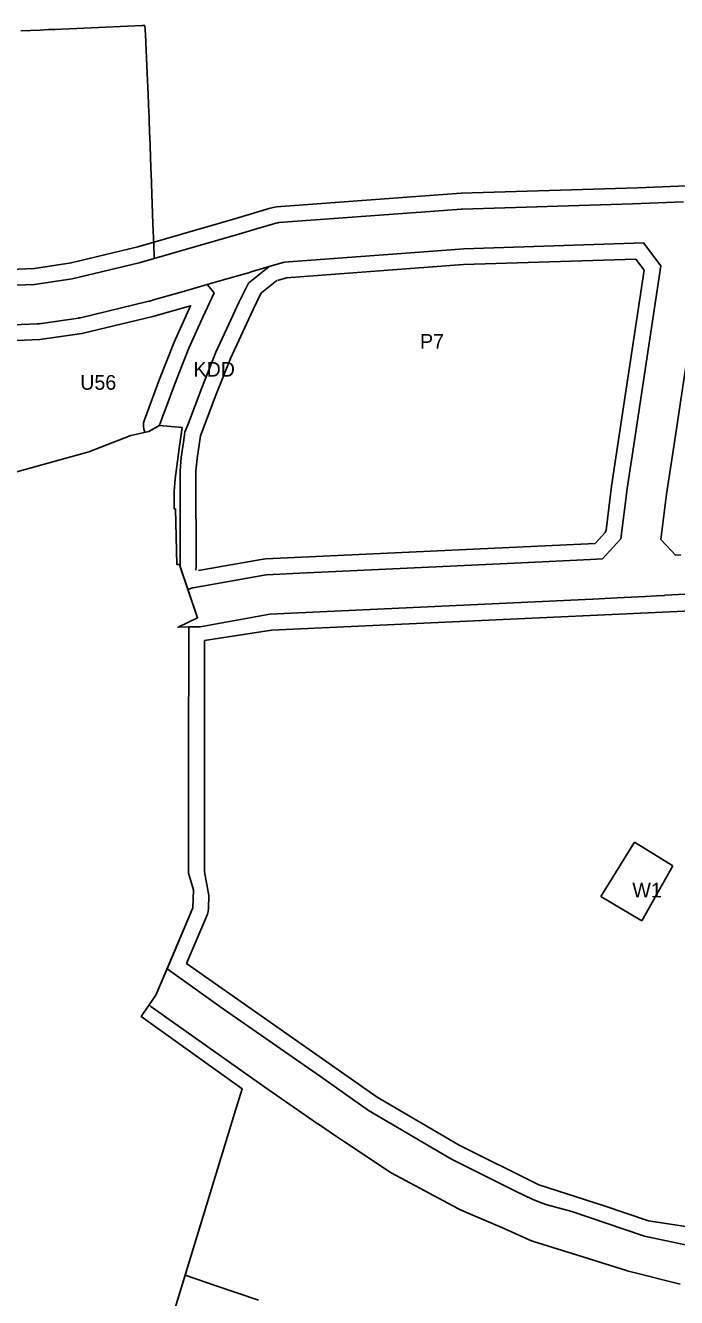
# Model space of a CAD drawing. Extents: x 7428103 to 7431580, y 5545880 to 5549002.
# Drawn here: x 7428892.8 to 7429139.1, y 5546219.5 to 5546701.1 of the extents above; entities that cross this region are included whole.
import ezdxf

# ---------------------------------------------------------------- set-up
doc = ezdxf.new("R2010")
doc.units = 0
for name, color, linetype in [('CZ_L_granica obszaru objętego planem', 7, 'Continuous'), ('CZ_L_linie rozgraniczające tereny o różnym przeznaczeniu oraz różnych warunkach ich zabudowy i zagospodarowania', 7, 'Continuous'), ('CZ_L_maksymalne nieprzekraczalne linie zabudowy', 7, 'Continuous'), ('CZ_L_opisy_linie rozgraniczające tereny o różnym przeznaczeniu oraz różnych warunkach ich zabudowy i zagospodarowania', 7, 'Continuous')]:
    doc.layers.add(name, color=color, linetype=linetype)

msp = doc.modelspace()

# ---------------------------------------------------------------- linework, layer by layer
at = {"layer": 'CZ_L_granica obszaru objętego planem'}
for p, q in [((7428943.45, 5546549.68), (7428939.45, 5546547.36)), ((7428952.02, 5546548.83), (7428943.45, 5546549.68)), ((7428932.66, 5546545.89), (7428916.75, 5546539.71)), ((7428939.45, 5546547.36), (7428932.66, 5546545.89)), ((7428950.98, 5546540.88), (7428952.02, 5546548.83)), ((7428949.49, 5546529.49), (7428950.98, 5546540.88)), ((7428916.75, 5546539.71), (7428884.44, 5546530.73)), ((7428949.1, 5546524.59), (7428949.49, 5546529.49)), ((7428949.01, 5546518.1), (7428949.1, 5546524.59)), ((7428949.54, 5546518.02), (7428949.01, 5546518.1)), ((7428950.1, 5546497), (7428949.54, 5546518.02)), ((7428951.06, 5546497.01), (7428950.1, 5546497)), ((7428957.94, 5546476.87), (7428951.06, 5546497.01)), ((7428950.54, 5546473.28), (7428957.94, 5546476.87)), ((7428954.57, 5546473.36), (7428950.54, 5546473.28)), ((7428954.56, 5546462.58), (7428954.57, 5546473.36)), ((7428954.53, 5546431.49), (7428954.56, 5546462.58)), ((7428954.53, 5546422.43), (7428954.53, 5546431.49)), ((7428954.49, 5546380.11), (7428954.53, 5546422.43)), ((7428956.31, 5546373.9), (7428954.49, 5546380.11)), ((7428956.09, 5546367.01), (7428956.31, 5546373.9)), ((7428942.16, 5546333.95), (7428956.09, 5546367.01)), ((7428936.55, 5546325.96), (7428942.16, 5546333.95)), ((7428974.81, 5546298.48), (7428936.55, 5546325.96)), ((7428971.91, 5546289.21), (7428974.81, 5546298.48)), ((7428945.19, 5546201.63), (7428971.91, 5546289.21))]:
    msp.add_line(p, q, dxfattribs=at)
at = {"layer": 'CZ_L_linie rozgraniczające tereny o różnym przeznaczeniu oraz różnych warunkach ich zabudowy i zagospodarowania'}
for p, q in [((7428891.05, 5546699.01), (7428898.31, 5546699.33)), ((7428898.31, 5546699.33), (7428901.54, 5546699.47)), ((7428901.54, 5546699.47), (7428903.86, 5546699.57)), ((7428903.86, 5546699.57), (7428906.43, 5546699.68)), ((7428906.43, 5546699.68), (7428912.22, 5546699.93)), ((7428912.22, 5546699.93), (7428914.83, 5546700.04)), ((7428914.83, 5546700.04), (7428936.95, 5546701.01)), ((7428936.95, 5546701.01), (7428937.99, 5546701.06)), ((7428937.99, 5546701.06), (7428938.15, 5546697.68)), ((7428938.15, 5546697.68), (7428938.72, 5546685.73)), ((7428938.72, 5546685.73), (7428939.25, 5546674.93)), ((7428939.25, 5546674.93), (7428939.52, 5546667.84)), ((7428939.52, 5546667.84), (7428939.52, 5546667.82)), ((7428939.52, 5546667.82), (7428939.55, 5546666.83)), ((7428939.55, 5546666.83), (7428939.62, 5546665.02)), ((7428939.62, 5546665.02), (7428939.63, 5546664.67)), ((7428939.63, 5546664.67), (7428939.86, 5546658.05)), ((7428939.86, 5546658.05), (7428939.88, 5546657.66)), ((7428939.88, 5546657.66), (7428939.91, 5546656.76)), ((7428939.91, 5546656.76), (7428939.95, 5546655.47)), ((7428939.95, 5546655.47), (7428940.25, 5546647.15)), ((7428940.25, 5546647.15), (7428940.43, 5546641.82)), ((7428940.43, 5546641.82), (7428940.45, 5546641.26)), ((7428940.45, 5546641.26), (7428941.03, 5546626.01)), ((7429047.51, 5546630.72), (7429057.66, 5546631.51)), ((7429057.66, 5546631.51), (7429057.94, 5546631.53)), ((7429057.94, 5546631.53), (7429058.01, 5546631.53)), ((7429058.01, 5546631.53), (7429122.49, 5546633.57)), ((7429122.49, 5546633.57), (7429141.68, 5546634.33)), ((7428988.69, 5546626.41), (7429047.51, 5546630.72)), ((7428941.03, 5546626.01), (7428941.33, 5546618.11)), ((7428941.52, 5546612.85), (7428973.83, 5546622.12)), ((7428973.83, 5546622.12), (7428980.19, 5546624.04)), ((7428980.19, 5546624.04), (7428987.08, 5546626.11)), ((7428987.08, 5546626.11), (7428987.48, 5546626.22)), ((7428987.48, 5546626.22), (7428987.96, 5546626.32)), ((7428987.96, 5546626.32), (7428988.44, 5546626.39)), ((7428988.44, 5546626.39), (7428988.69, 5546626.41)), ((7428941.33, 5546618.11), (7428941.51, 5546613.1)), ((7429058.66, 5546616.55), (7429123, 5546618.58)), ((7429123, 5546618.58), (7429123.05, 5546618.58)), ((7429123.05, 5546618.58), (7429126.59, 5546618.72)), ((7429126.59, 5546618.72), (7429133.16, 5546610.02)), ((7428941.52, 5546612.85), (7428935.83, 5546611.21)), ((7428941.51, 5546613.1), (7428941.52, 5546612.85)), ((7428990.61, 5546611.51), (7429048.63, 5546615.76)), ((7429048.63, 5546615.76), (7429048.67, 5546615.76)), ((7429048.67, 5546615.76), (7429058.66, 5546616.55)), ((7428933.17, 5546610.57), (7428910.44, 5546605.09)), ((7428935.83, 5546611.21), (7428933.17, 5546610.57)), ((7428966.36, 5546604.37), (7428978.01, 5546607.72)), ((7428977.13, 5546603.54), (7428984.97, 5546609.81)), ((7428978.01, 5546607.72), (7428978.1, 5546607.75)), ((7428978.1, 5546607.75), (7428979.39, 5546608.14)), ((7428979.39, 5546608.14), (7428984.97, 5546609.81)), ((7428984.97, 5546609.81), (7428990.61, 5546611.51)), ((7429133.16, 5546610.02), (7429123.46, 5546545.53)), ((7429138.29, 5546543.29), (7429148.42, 5546610.65)), ((7428896.25, 5546603.05), (7428868.81, 5546601.94)), ((7428910.44, 5546605.09), (7428896.25, 5546603.05)), ((7428958.12, 5546602.01), (7428961.54, 5546602.99)), ((7428961.54, 5546602.99), (7428966.36, 5546604.37)), ((7428961.54, 5546602.99), (7428964.15, 5546599.8)), ((7428973.47, 5546596.13), (7428977.13, 5546603.54)), ((7428941.17, 5546597.14), (7428951.18, 5546600.01)), ((7428951.18, 5546600.01), (7428958.12, 5546602.01)), ((7428964.15, 5546599.8), (7428959.85, 5546590.57)), ((7428913.61, 5546590.43), (7428933.74, 5546595.28)), ((7428933.74, 5546595.28), (7428939.5, 5546596.67)), ((7428939.5, 5546596.67), (7428939.81, 5546596.75)), ((7428939.5, 5546596.67), (7428939.5, 5546596.67)), ((7428939.81, 5546596.75), (7428941.17, 5546597.14)), ((7428968.92, 5546586.35), (7428973.47, 5546596.13)), ((7428870.63, 5546587), (7428897.25, 5546588.08)), ((7428897.25, 5546588.08), (7428897.73, 5546588.12)), ((7428897.73, 5546588.12), (7428898.01, 5546588.15)), ((7428898.01, 5546588.15), (7428912.92, 5546590.29)), ((7428912.92, 5546590.29), (7428913.13, 5546590.33)), ((7428913.13, 5546590.33), (7428913.61, 5546590.43)), ((7428959.85, 5546590.57), (7428954.59, 5546578.93)), ((7428964.83, 5546577.37), (7428968.92, 5546586.35)), ((7428954.59, 5546578.93), (7428951.09, 5546569.95)), ((7428959.51, 5546563.93), (7428964.83, 5546577.37)), ((7428951.09, 5546569.95), (7428949.15, 5546565)), ((7428949.15, 5546565), (7428945.87, 5546556.18)), ((7428954.42, 5546550.54), (7428959.51, 5546563.93)), ((7428945.87, 5546556.18), (7428944.65, 5546552.89)), ((7428943.72, 5546550.39), (7428943.41, 5546549.66)), ((7428944.65, 5546552.89), (7428943.72, 5546550.39)), ((7428953.11, 5546547.07), (7428954.42, 5546550.54)), ((7428952.53, 5546543.28), (7428953.11, 5546547.07)), ((7429123.46, 5546545.53), (7429120.42, 5546525.82)), ((7428951.73, 5546537.49), (7428952.53, 5546543.28)), ((7429135.26, 5546523.65), (7429138.29, 5546543.27)), ((7429138.29, 5546543.27), (7429138.29, 5546543.29)), ((7428951.3, 5546532.51), (7428951.73, 5546537.49)), ((7428951.36, 5546528.96), (7428951.3, 5546532.51)), ((7428951.34, 5546519.82), (7428951.36, 5546528.96)), ((7429120.39, 5546525.59), (7429118.07, 5546506.75)), ((7429120.42, 5546525.82), (7429120.39, 5546525.59)), ((7429133.15, 5546506.5), (7429135.26, 5546523.65)), ((7428951.34, 5546510.5), (7428951.34, 5546519.82)), ((7428951.37, 5546498.1), (7428951.34, 5546510.5)), ((7429118.07, 5546506.75), (7429111.13, 5546499.13)), ((7429138.7, 5546500.57), (7429133.15, 5546506.5)), ((7428951.38, 5546496.09), (7428951.37, 5546498.1)), ((7429080.39, 5546497.66), (7428993.89, 5546493.59)), ((7429106.61, 5546498.89), (7429080.39, 5546497.66)), ((7429111.13, 5546499.13), (7429106.61, 5546498.89)), ((7429140.7, 5546500.67), (7429138.7, 5546500.57)), ((7428983.04, 5546493.01), (7428956.22, 5546488.22)), ((7428983.11, 5546493.02), (7428983.04, 5546493.01)), ((7428983.12, 5546493.02), (7428983.11, 5546493.02)), ((7428983.11, 5546493.02), (7428983.11, 5546493.02)), ((7428983.14, 5546493.03), (7428983.12, 5546493.02)), ((7428983.12, 5546493.02), (7428983.12, 5546493.02)), ((7428983.89, 5546493.11), (7428983.14, 5546493.03)), ((7428983.91, 5546493.11), (7428983.89, 5546493.11)), ((7428983.99, 5546493.12), (7428983.91, 5546493.11)), ((7428984, 5546493.12), (7428983.99, 5546493.12)), ((7428993.89, 5546493.59), (7428984, 5546493.12)), ((7428954.4, 5546487.64), (7428954.28, 5546487.58)), ((7428954.57, 5546487.71), (7428954.4, 5546487.64)), ((7428956.04, 5546488.17), (7428954.57, 5546487.71)), ((7428956.13, 5546488.19), (7428956.04, 5546488.17)), ((7428956.22, 5546488.22), (7428956.13, 5546488.19)), ((7428985.2, 5546478.16), (7429107.34, 5546483.91)), ((7429107.34, 5546483.91), (7429107.34, 5546483.91)), ((7429107.34, 5546483.91), (7429107.36, 5546483.91)), ((7429107.36, 5546483.91), (7429107.37, 5546483.91)), ((7429107.37, 5546483.91), (7429107.38, 5546483.91)), ((7429107.38, 5546483.91), (7429116.63, 5546484.4)), ((7429116.63, 5546484.4), (7429124.61, 5546484.81)), ((7429124.61, 5546484.81), (7429127.31, 5546484.95)), ((7429127.31, 5546484.95), (7429131.46, 5546485.16)), ((7429131.46, 5546485.16), (7429134.6, 5546485.32)), ((7429134.6, 5546485.32), (7429134.67, 5546485.34)), ((7429134.67, 5546485.34), (7429142.51, 5546485.75)), ((7428958.86, 5546473.45), (7428985.2, 5546478.16)), ((7428954.57, 5546473.36), (7428957.55, 5546473.36)), ((7428957.55, 5546473.36), (7428957.85, 5546473.34)), ((7428957.85, 5546473.34), (7428957.9, 5546473.35)), ((7428957.9, 5546473.35), (7428957.95, 5546473.35)), ((7428957.95, 5546473.35), (7428958.76, 5546473.44)), ((7428958.76, 5546473.44), (7428958.78, 5546473.44)), ((7428958.78, 5546473.44), (7428958.86, 5546473.45)), ((7429110.5, 5546371.36), (7429123.17, 5546391.9)), ((7429123.17, 5546391.9), (7429137.74, 5546382.98)), ((7429137.74, 5546382.98), (7429125.94, 5546362.11)), ((7429125.94, 5546362.11), (7429110.5, 5546371.36)), ((7428968.1, 5546328.41), (7428946.35, 5546343.9)), ((7428939.78, 5546330.15), (7428939.63, 5546330.36)), ((7428940.28, 5546329.75), (7428939.78, 5546330.15)), ((7428983.36, 5546299.19), (7428940.28, 5546329.75)), ((7429004.43, 5546303.16), (7428968.1, 5546328.41)), ((7428983.37, 5546299.18), (7428983.36, 5546299.19)), ((7428983.4, 5546299.16), (7428983.37, 5546299.18)), ((7429003.56, 5546285.15), (7428983.4, 5546299.16)), ((7429022.55, 5546290.31), (7429004.43, 5546303.16)), ((7429054, 5546271.87), (7429022.55, 5546290.31)), ((7429003.58, 5546285.14), (7429003.56, 5546285.15)), ((7429003.62, 5546285.11), (7429003.58, 5546285.14)), ((7429010.48, 5546280.5), (7429003.62, 5546285.11)), ((7429013.1, 5546278.74), (7429010.48, 5546280.5)), ((7429013.11, 5546278.74), (7429013.1, 5546278.74)), ((7429013.12, 5546278.72), (7429013.11, 5546278.74)), ((7429030.81, 5546267), (7429013.12, 5546278.72)), ((7429078.24, 5546259.83), (7429054, 5546271.87)), ((7429031.03, 5546266.89), (7429030.81, 5546267)), ((7429031.2, 5546266.76), (7429031.03, 5546266.89)), ((7429056.38, 5546253.22), (7429031.2, 5546266.76)), ((7429084.7, 5546256.65), (7429078.24, 5546259.83)), ((7429089.63, 5546254.73), (7429084.7, 5546256.65)), ((7429056.68, 5546253.08), (7429056.38, 5546253.22)), ((7429056.75, 5546253.04), (7429056.68, 5546253.08)), ((7429074.09, 5546245.48), (7429056.75, 5546253.04)), ((7429099.53, 5546252.08), (7429089.63, 5546254.73)), ((7429119.16, 5546245.39), (7429099.53, 5546252.08)), ((7429084.51, 5546240.93), (7429074.09, 5546245.48)), ((7429127.03, 5546242.77), (7429119.16, 5546245.39)), ((7429143.67, 5546239.19), (7429127.03, 5546242.77)), ((7429084.78, 5546240.88), (7429084.51, 5546240.93)), ((7429085.01, 5546240.74), (7429084.78, 5546240.88)), ((7429099.66, 5546236.15), (7429085.01, 5546240.74)), ((7429120.15, 5546229.72), (7429099.66, 5546236.15)), ((7428953.23, 5546227.96), (7428964.94, 5546223.92)), ((7428954.31, 5546227.58), (7428954.31, 5546227.58)), ((7429120.19, 5546229.72), (7429120.15, 5546229.72)), ((7429120.43, 5546229.64), (7429120.19, 5546229.72)), ((7429140.5, 5546224.63), (7429120.43, 5546229.64)), ((7428964.94, 5546223.92), (7428980.96, 5546218.51))]:
    msp.add_line(p, q, dxfattribs=at)
for points in [[(7428943.41, 5546549.66), (7428939.45, 5546547.36), (7428932.66, 5546545.89), (7428916.75, 5546539.71), (7428884.44, 5546530.73), (7428871.36, 5546583.78), (7428870.63, 5546587)], [(7428951.38, 5546496.09), (7428951.06, 5546497.01), (7428950.1, 5546497), (7428949.54, 5546518.02), (7428949.01, 5546518.1), (7428949.1, 5546524.59), (7428949.49, 5546529.49), (7428950.98, 5546540.88), (7428952.02, 5546548.83), (7428943.45, 5546549.68), (7428943.41, 5546549.66)], [(7428954.28, 5546487.58), (7428951.38, 5546496.09)], [(7428954.57, 5546473.36), (7428950.54, 5546473.28), (7428957.94, 5546476.87), (7428954.28, 5546487.58)], [(7428946.35, 5546343.9), (7428956.09, 5546367.01), (7428956.31, 5546373.9), (7428954.49, 5546380.11), (7428954.53, 5546422.43), (7428954.53, 5546431.49), (7428954.56, 5546462.58), (7428954.57, 5546473.36)], [(7428939.63, 5546330.36), (7428942.16, 5546333.95), (7428946.35, 5546343.9)], [(7428942.53, 5546192.87), (7428971.91, 5546289.21), (7428974.81, 5546298.48), (7428936.55, 5546325.96), (7428939.63, 5546330.36)]]:
    msp.add_lwpolyline(points, dxfattribs=at)
at = {"layer": 'CZ_L_maksymalne nieprzekraczalne linie zabudowy'}
for points in [[(7428868.34, 5546607.92), (7428896.21, 5546609.11), (7428910.11, 5546611.18), (7428935.35, 5546617.31), (7428972.44, 5546627.97), (7428985.35, 5546631.86), (7428987.81, 5546632.35), (7429057.59, 5546637.52), (7429124.34, 5546639.65), (7429204.75, 5546642.82), (7429345.79, 5546648.72), (7429351.88, 5546649), (7429381.55, 5546652.01), (7429423.97, 5546654.12), (7429426.89, 5546653.93), (7429435.55, 5546652.43), (7429441.84, 5546651.07)], [(7428958.28, 5546494.68), (7428982.01, 5546498.92), (7428983.71, 5546499.11), (7429108.31, 5546504.99), (7429112.11, 5546509.12), (7429112.42, 5546510), (7429114.49, 5546526.71), (7429126.82, 5546608.45), (7429123.66, 5546612.6), (7429058.47, 5546610.51), (7428991.57, 5546605.53), (7428988.15, 5546604.51)], [(7428987.93, 5546604.49), (7428982.2, 5546599.92), (7428981.77, 5546599.39), (7428978.88, 5546593.54), (7428970.35, 5546575.03), (7428964.86, 5546561.12), (7428959, 5546545.67), (7428957.73, 5546537.09), (7428957.31, 5546532.31), (7428957.38, 5546496.13), (7428957.25, 5546494.87)], [(7428937.98, 5546547.1), (7428937.57, 5546548.26), (7428937.41, 5546549.41), (7428937.48, 5546550.6), (7428937.78, 5546551.73), (7428943.56, 5546567.16), (7428949.01, 5546581.13), (7428955.27, 5546594.95), (7428941.02, 5546590.86), (7428914.14, 5546584.41), (7428898.19, 5546582.13), (7428872.12, 5546581.06)], [(7429216.04, 5546482.7), (7428985.81, 5546472.18), (7428960.56, 5546468.22), (7428960.49, 5546380.68), (7428962.19, 5546371.75), (7428962.09, 5546366.82), (7428961.94, 5546365.69), (7428961.62, 5546364.68), (7428953.76, 5546346.02), (7429025.8, 5546295.36), (7429056.85, 5546277.16), (7429086.96, 5546262.22), (7429111.73, 5546254.26), (7429128.46, 5546248.62), (7429158.31, 5546243.98)]]:
    msp.add_lwpolyline(points, dxfattribs=at)

# ---------------------------------------------------------------- texts
at = {"layer": 'CZ_L_opisy_linie rozgraniczające tereny o różnym przeznaczeniu oraz różnych warunkach ich zabudowy i zagospodarowania'}
for s, p in [('P7', (7429042.06, 5546578.74)), ('KDD', (7428956.36, 5546568.13)), ('U56', (7428913.52, 5546563.16)), ('W1', (7429122.39, 5546370.96))]:
    msp.add_text(s, height=5.549, dxfattribs=at).set_placement(p)

doc.saveas('drawing.dxf')
